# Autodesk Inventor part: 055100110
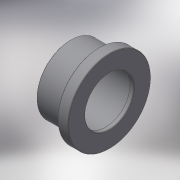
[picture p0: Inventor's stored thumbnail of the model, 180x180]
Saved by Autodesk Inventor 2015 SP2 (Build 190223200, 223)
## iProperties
Created: 2017-10
Part Number: 055100110
Material: Generic
Description: PLASSON FLANGE FLAT AD.-CEM 110
Document SubType Name: Modeling
Designer: KIM
Mass: 266.674 g
Surface Area: 686.706 cm^2
Volume: 266.674 cm^3
Density: 1 g/cm^3
Appearance: Default
Author: KIM
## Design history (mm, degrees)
derived "055100.ipt"
feature "Solid1::055100.ipt"
tag "TaggingFeature1"
body "Solid1"
other parameters: "d0" = 66, "d1" = 126, "d3" = 99, "d4" = 12, "d5" = 61, "d8" = 1.1, "E_" = 126, "l_" = 61, "B_" = 12, "H_" = 66
